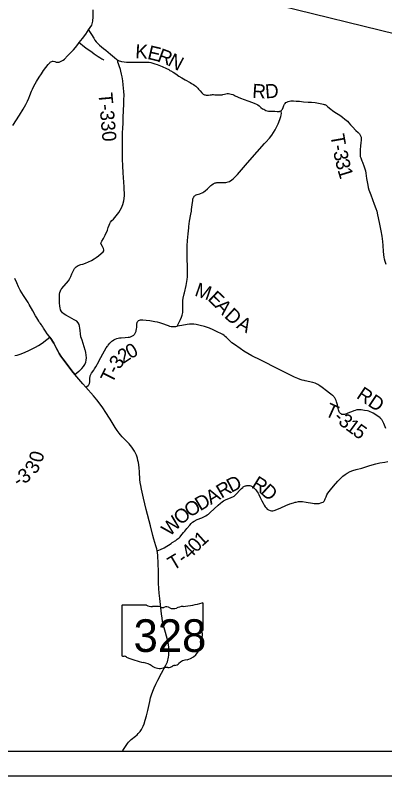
# Model space of a CAD drawing. Extents: x 0 to 34, y 0 to 22.
# Drawn here: x 5.01 to 6.504, y 14.105 to 17.181 of the extents above; entities that cross this region are included whole.
import ezdxf

# ---------------------------------------------------------------- set-up
doc = ezdxf.new("R2010")
doc.units = 0
for name, color, linetype in [('GM_X_State_Location', 7, 'Continuous'), ('GM_X_State_Route', 7, 'Continuous'), ('GM_X_State_Shield', 7, 'Continuous'), ('GM_X_Township_Road', 7, 'Continuous'), ('GM_X_Township_Road_Text', 7, 'Continuous'), ('SH_Data', 7, 'Continuous'), ('SH_Text', 7, 'Continuous')]:
    doc.layers.add(name, color=color, linetype=linetype)

msp = doc.modelspace()

# ---------------------------------------------------------------- linework, layer by layer
at = {"layer": 'GM_X_State_Route'}
for points in [[(5.18, 16.9909), (5.182, 16.9906), (5.1849, 16.9907), (5.1879, 16.9912), (5.1907, 16.992), (5.1935, 16.9932), (5.1988, 16.9961), (5.2038, 16.9997), (5.2085, 17.0037), (5.2216, 17.0168), (5.2451, 17.0414), (5.2534, 17.0505), (5.2631, 17.0625), (5.2689, 17.07), (5.2819, 17.087), (5.2948, 17.1043), (5.3018, 17.1145), (5.306, 17.1215), (5.3192, 17.1407), (5.3242, 17.1566), (5.3254, 17.1744), (5.3247, 17.2033)], [(5.0005, 16.7353), (5.0271, 16.7772), (5.0415, 16.8011), (5.0522, 16.82), (5.0594, 16.8337), (5.0648, 16.8449), (5.0694, 16.8563), (5.0761, 16.8737), (5.0798, 16.8822), (5.0854, 16.8934), (5.096, 16.9124), (5.107, 16.931), (5.1155, 16.944), (5.1245, 16.9567), (5.134, 16.969), (5.1435, 16.9812), (5.1496, 16.9883), (5.1518, 16.9907), (5.1544, 16.9927), (5.1574, 16.994), (5.1607, 16.9947), (5.1639, 16.9945), (5.1701, 16.9932), (5.176, 16.9915), (5.179, 16.991), (5.18, 16.9909)], [(5.1495, 15.8791), (5.1468, 15.8825), (5.1394, 15.8924), (5.1324, 15.9028), (5.1245, 15.916), (5.1211, 15.921), (5.1173, 15.9257), (5.1157, 15.9285), (5.1101, 15.9358), (5.1085, 15.9385), (5.1071, 15.9414), (5.105, 15.9439), (5.0968, 15.9577), (5.0921, 15.9659), (5.0805, 15.9854), (5.0666, 16.0109), (5.0618, 16.0189), (5.0431, 16.0474), (5.0304, 16.069), (5.0232, 16.0827), (5.0158, 16.0988), (5.0089, 16.1158)], [(5.2023, 15.7918), (5.1945, 15.8023), (5.1876, 15.8127), (5.1829, 15.8207), (5.1762, 15.8333), (5.1657, 15.8546), (5.1612, 15.8626), (5.1561, 15.8703), (5.1495, 15.8791)], [(5.2506, 15.7282), (5.2388, 15.7427), (5.2238, 15.7625), (5.2023, 15.7918)], [(5.3937, 15.5479), (5.3916, 15.5514), (5.3765, 15.5749), (5.3643, 15.5929), (5.3534, 15.6079), (5.3401, 15.6251), (5.3261, 15.6417), (5.2954, 15.6767), (5.2831, 15.6907), (5.2506, 15.7282)], [(5.443, 14.2054), (5.4448, 14.208), (5.4638, 14.2364), (5.4677, 14.2414), (5.472, 14.2459), (5.4791, 14.2521), (5.4961, 14.2656), (5.5031, 14.2717), (5.5076, 14.2759), (5.5117, 14.2805), (5.5156, 14.2852), (5.5207, 14.2929), (5.5238, 14.2982), (5.5276, 14.3066), (5.5308, 14.3153), (5.5355, 14.3301), (5.5404, 14.348), (5.5455, 14.3691), (5.5536, 14.4055), (5.5575, 14.4205), (5.5612, 14.4324), (5.5663, 14.4471), (5.572, 14.4616), (5.5783, 14.4758), (5.5864, 14.4927), (5.6009, 14.5201), (5.6188, 14.5528), (5.6229, 14.5611), (5.6253, 14.5668), (5.6272, 14.5726), (5.6288, 14.5785), (5.63, 14.5845), (5.6312, 14.5936), (5.6316, 14.6029), (5.6314, 14.6121), (5.6305, 14.6245), (5.6291, 14.6368), (5.6274, 14.6459), (5.624, 14.661), (5.6152, 14.694), (5.6087, 14.718), (5.6059, 14.7301), (5.6037, 14.7423), (5.6011, 14.7608), (5.594, 14.8225), (5.592, 14.8442), (5.5907, 14.8628), (5.5899, 14.8845), (5.589, 14.9197), (5.5887, 14.9311), (5.586, 14.9962), (5.5851, 15.0085), (5.5842, 15.015), (5.5823, 15.0236), (5.5791, 15.0355), (5.5709, 15.0623), (5.5669, 15.0773), (5.557, 15.1164), (5.5397, 15.1825), (5.5285, 15.2277), (5.5203, 15.2641), (5.5173, 15.2794), (5.5155, 15.2917), (5.5143, 15.3041), (5.5128, 15.3351), (5.5115, 15.3506), (5.5099, 15.3629), (5.5084, 15.372), (5.5063, 15.381), (5.5038, 15.3899), (5.4998, 15.4017), (5.4963, 15.4102), (5.4921, 15.4184), (5.4873, 15.4263), (5.482, 15.4339), (5.4763, 15.4412), (5.4703, 15.4483), (5.4618, 15.4573), (5.4418, 15.4766), (5.4355, 15.4836), (5.4296, 15.4909), (5.4224, 15.5011), (5.414, 15.5142), (5.3937, 15.5479)]]:
    msp.add_lwpolyline(points, dxfattribs=at)
at = {"layer": 'GM_X_State_Shield'}
for p, q in [((5.5406, 14.7959), (5.4441, 14.7959)), ((5.7705, 14.6962), (5.7705, 14.8009)), ((5.4409, 14.7925), (5.4409, 14.5923)), ((5.7704, 14.6962), (5.7705, 14.6962))]:
    msp.add_line(p, q, dxfattribs=at)
for centre, major_axis, start_param, end_param in [((5.4447, 14.7929), (0.00382, 0), 1.712693, 3.28349), ((5.5636, 14.8191), (0.037, 0), 4.042523, 4.731795), ((5.6531, 15.0687), (0.3495, 0), 4.814394, 5.042369), ((5.7668, 14.8013), (0.00367, 0), 6.141152, 7.989035), ((5.5759, 14.6835), (0.133, 0), 1.404758, 1.657858), ((5.6061, 14.7939), (0.0107, 0), 3.836095, 5.185415), ((5.6218, 14.7708), (0.0222, 0), 0.950623, 2.079405), ((5.6504, 14.8025), (0.0267, 0), 4.081561, 5.145723), ((5.6976, 14.7348), (0.0703, 0), 1.699011, 2.107814), ((5.7696, 14.6885), (0.00568, 0), 1.883978, 3.671073), ((5.7335, 14.6753), (0.0341, 0), 5.934695, 6.695948), ((5.7665, 14.6958), (0.00393, 0), 5.05454, 6.418171), ((5.6726, 14.639), (0.0874, 0), 5.101752, 6.440018), ((5.7836, 14.6524), (0.0248, 0), 2.387724, 3.262537), ((5.4447, 14.5919), (0.00385, 0), 3.00124, 4.508301), ((5.4453, 14.6124), (0.0294, 0), 4.665946, 4.897461), ((5.4513, 14.5808), (0.0106, 0), 0.519207, 1.627899), ((5.5851, 14.7606), (0.2524, 0), 4.195997, 4.488961), ((5.5099, 14.5024), (0.079, 0), 0.823519, 1.323587), ((5.5953, 14.5798), (0.0501, 0), 4.026481, 4.996735), ((5.6279, 14.5648), (0.0267, 0), 4.691044, 5.507374), ((5.652, 14.5454), (0.00752, 0), 1.147584, 2.315152), ((5.6488, 14.5729), (0.0282, 0), 4.937069, 5.64225), ((5.7095, 14.5362), (0.0479, 0), 1.647645, 2.488434), ((5.6242, 14.5106), (0.0412, 0), 1.495662, 1.94098)]:
    msp.add_ellipse(centre, major_axis=major_axis, ratio=0.8, start_param=start_param, end_param=end_param, dxfattribs=at)
at = {"layer": 'GM_X_Township_Road'}
for points in [[(5.306, 17.1215), (5.3127, 17.1109), (5.3177, 17.1031), (5.3271, 17.0875), (5.332, 17.0802), (5.3375, 17.0729), (5.3438, 17.0661), (5.3506, 17.0601), (5.367, 17.0469), (5.3762, 17.0396), (5.3947, 17.0239), (5.4111, 17.0098), (5.4209, 17.0018), (5.4254, 16.9986), (5.4298, 16.9968), (5.4354, 16.9952), (5.4399, 16.994), (5.4413, 16.9937), (5.4505, 16.9921), (5.4597, 16.9913), (5.469, 16.9909), (5.495, 16.9911), (5.5217, 16.9917), (5.5403, 16.9917), (5.5446, 16.9913), (5.5509, 16.9905), (5.5581, 16.9894), (5.5664, 16.9874), (5.5747, 16.9848), (5.5835, 16.9818), (5.6043, 16.9737), (5.6215, 16.9654), (5.6308, 16.9608), (5.6357, 16.9579), (5.6394, 16.9554), (5.6484, 16.9503), (5.6592, 16.9433), (5.6718, 16.9349), (5.6837, 16.9275), (5.6964, 16.9202), (5.717, 16.9087), (5.7233, 16.9053), (5.7309, 16.9006), (5.7365, 16.8968), (5.7407, 16.8935), (5.7449, 16.8897), (5.748, 16.8861), (5.7515, 16.8818), (5.7571, 16.8748), (5.7639, 16.8667), (5.7667, 16.8638), (5.7696, 16.8615), (5.7721, 16.8603), (5.7748, 16.8594), (5.7774, 16.8588), (5.7814, 16.8582), (5.7858, 16.8579), (5.7917, 16.8582), (5.7985, 16.859), (5.804, 16.8595), (5.8071, 16.8597), (5.8114, 16.8597), (5.8164, 16.8596), (5.8253, 16.8596), (5.8363, 16.8595), (5.8421, 16.8595), (5.846, 16.8596), (5.85, 16.86), (5.8558, 16.862), (5.8614, 16.8633), (5.8673, 16.8638), (5.8728, 16.8637), (5.8778, 16.8632), (5.8829, 16.8623), (5.8893, 16.8603), (5.8954, 16.8575), (5.8993, 16.8554), (5.9213, 16.8452), (5.9504, 16.8346), (5.9687, 16.8277), (5.9781, 16.8241), (5.9857, 16.8208), (5.9915, 16.8181), (5.9968, 16.8142), (6.0036, 16.808), (6.0104, 16.803), (6.0145, 16.8004), (6.0186, 16.7978), (6.023, 16.7957), (6.0284, 16.794), (6.0334, 16.793), (6.0403, 16.7927), (6.0516, 16.7924), (6.0601, 16.7923), (6.0687, 16.7921), (6.0734, 16.7921), (6.078, 16.7921), (6.0803, 16.7924), (6.0843, 16.7941), (6.0866, 16.796), (6.0884, 16.7982), (6.0904, 16.8012), (6.0931, 16.8079), (6.0955, 16.8157), (6.0969, 16.8184), (6.099, 16.8215), (6.101, 16.8242), (6.1043, 16.8273), (6.1075, 16.8294), (6.1105, 16.831), (6.1138, 16.8322), (6.1185, 16.8336), (6.1242, 16.8343), (6.1293, 16.8345), (6.1357, 16.8344), (6.1459, 16.8339), (6.1539, 16.8332), (6.1592, 16.8328), (6.1761, 16.8312), (6.1946, 16.8298), (6.2084, 16.8289), (6.2224, 16.8277), (6.2366, 16.8257), (6.2497, 16.8232), (6.2557, 16.8216), (6.2597, 16.8202), (6.2615, 16.8195), (6.2643, 16.8182), (6.2669, 16.8166), (6.2695, 16.8149), (6.2742, 16.811), (6.286, 16.8007), (6.2922, 16.7954), (6.2981, 16.7912), (6.3094, 16.7845), (6.3221, 16.7771), (6.3339, 16.7685), (6.3425, 16.761), (6.3529, 16.7522), (6.3591, 16.7454), (6.3653, 16.7379), (6.3708, 16.7321), (6.374, 16.729), (6.3872, 16.7154), (6.396, 16.7072), (6.3995, 16.7041), (6.4017, 16.7016), (6.4036, 16.6992), (6.4052, 16.6965), (6.4066, 16.6938), (6.4076, 16.6909), (6.4083, 16.688), (6.4088, 16.685), (6.4089, 16.682), (6.4087, 16.6758), (6.4077, 16.6646), (6.4064, 16.6523), (6.405, 16.6368), (6.4046, 16.6275), (6.4045, 16.6217), (6.4046, 16.6153), (6.4053, 16.61), (6.4068, 16.6047), (6.4086, 16.5998), (6.4117, 16.5915), (6.4137, 16.5868), (6.4211, 16.5677), (6.4236, 16.5599), (6.4259, 16.5512), (6.4277, 16.5422), (6.4291, 16.5313), (6.4304, 16.5206), (6.4326, 16.5073), (6.4355, 16.4931), (6.4375, 16.484), (6.4402, 16.4751), (6.4477, 16.4548), (6.4615, 16.4173), (6.4678, 16.3998), (6.4714, 16.3879), (6.4752, 16.3731), (6.4819, 16.3432), (6.4886, 16.3095), (6.4927, 16.288), (6.494, 16.277), (6.4952, 16.2661), (6.4965, 16.2491), (6.4982, 16.2256), (6.4988, 16.2139), (6.5005, 16.2017), (6.5018, 16.1956), (6.5042, 16.1867), (6.5083, 16.1749)], [(5.2689, 17.07), (5.2735, 17.0663), (5.2833, 17.0585), (5.2959, 17.0493), (5.3216, 17.0315), (5.3295, 17.0252), (5.3456, 17.0137), (5.352, 17.0097), (5.3601, 17.0049), (5.3652, 17.0015), (5.3676, 16.9995)], [(5.4433, 16.6481), (5.4436, 16.6658), (5.444, 16.6872), (5.4443, 16.705), (5.445, 16.7245), (5.4457, 16.7443), (5.4467, 16.7691), (5.4473, 16.794), (5.4489, 16.8225), (5.4494, 16.839), (5.4499, 16.8571), (5.4495, 16.8724), (5.4479, 16.886), (5.4464, 16.8995), (5.4444, 16.9157), (5.4422, 16.9319), (5.4401, 16.9431), (5.4375, 16.9553), (5.4358, 16.9613), (5.4302, 16.9765), (5.4272, 16.9847), (5.4254, 16.9907), (5.4251, 16.9949), (5.4254, 16.9986)], [(6.5088, 15.5102), (6.4999, 15.5298), (6.4961, 15.538), (6.4933, 15.5435), (6.4916, 15.546), (6.4896, 15.5484), (6.4874, 15.5506), (6.4851, 15.5526), (6.4801, 15.5563), (6.4568, 15.5717), (6.4513, 15.5747), (6.4457, 15.5772), (6.4398, 15.5792), (6.4338, 15.5807), (6.4216, 15.5831), (6.4093, 15.585), (6.4031, 15.5855), (6.3969, 15.5854), (6.3908, 15.5846), (6.3847, 15.5831), (6.3788, 15.5812), (6.3701, 15.5778), (6.3617, 15.574), (6.3517, 15.5702), (6.3456, 15.568), (6.3416, 15.5669), (6.3381, 15.5664), (6.3361, 15.5662), (6.3344, 15.5664), (6.3312, 15.567), (6.3278, 15.5684), (6.3249, 15.5704), (6.3227, 15.5726), (6.321, 15.5751), (6.3197, 15.5776), (6.3185, 15.5809), (6.3174, 15.585), (6.3162, 15.5903), (6.3127, 15.6054), (6.3095, 15.6174), (6.3074, 15.6233), (6.3048, 15.6289), (6.3016, 15.6342), (6.2998, 15.6367), (6.2978, 15.639), (6.2956, 15.6412), (6.2933, 15.6433), (6.2909, 15.6452), (6.2807, 15.6523), (6.2682, 15.6615), (6.2511, 15.675), (6.2412, 15.6825), (6.2334, 15.6876), (6.2279, 15.6904), (6.2221, 15.6927), (6.2131, 15.6953), (6.1828, 15.7021), (6.1783, 15.7032), (6.1708, 15.7052), (6.1619, 15.708), (6.1532, 15.7115), (6.1391, 15.7179), (6.075, 15.7496), (6.0028, 15.7858), (5.9668, 15.8042), (5.9505, 15.8132), (5.9345, 15.8228), (5.9189, 15.8331), (5.896, 15.8491), (5.886, 15.8565), (5.8789, 15.8625), (5.8744, 15.8668), (5.8636, 15.878), (5.859, 15.8822), (5.8542, 15.8861), (5.8491, 15.8896), (5.841, 15.8941), (5.8298, 15.8997), (5.8101, 15.9088), (5.7958, 15.9149), (5.787, 15.9181), (5.7751, 15.9218), (5.7571, 15.9265), (5.7419, 15.9298), (5.7327, 15.9314), (5.7265, 15.9321), (5.7203, 15.9322), (5.7141, 15.9318), (5.7049, 15.9306), (5.6835, 15.9267), (5.6641, 15.9236), (5.6696, 15.9338), (5.6759, 15.9448), (5.6786, 15.9509), (5.6819, 15.9599), (5.6845, 15.9675), (5.6862, 15.9739), (5.6873, 15.9792), (5.6879, 15.9832), (5.6881, 15.992), (5.6876, 16.0083), (5.6878, 16.0218), (5.6881, 16.0271), (5.6894, 16.0364), (5.6928, 16.0537), (5.6939, 16.0586), (5.7007, 16.0879), (5.7038, 16.1041), (5.7053, 16.1118), (5.7065, 16.1233), (5.707, 16.1335), (5.7071, 16.1408), (5.7067, 16.1525), (5.7064, 16.1668), (5.7055, 16.1945), (5.705, 16.2273), (5.7054, 16.248), (5.7063, 16.2697), (5.709, 16.2972), (5.7114, 16.3205), (5.7124, 16.3271), (5.7148, 16.3477), (5.7199, 16.376), (5.722, 16.3881), (5.7233, 16.3947), (5.7259, 16.4145), (5.7276, 16.4311), (5.7287, 16.437), (5.7295, 16.4405), (5.7305, 16.4434), (5.7316, 16.4454), (5.7323, 16.4468), (5.7339, 16.4489), (5.7362, 16.4511), (5.7391, 16.4534), (5.7416, 16.4547), (5.7451, 16.4557), (5.757, 16.4588), (5.7681, 16.4635), (5.7732, 16.4669), (5.778, 16.4708), (5.7871, 16.4791), (5.8006, 16.4917), (5.8054, 16.4955), (5.8106, 16.4989), (5.8133, 16.5003), (5.8161, 16.5015), (5.819, 16.5026), (5.822, 16.5035), (5.825, 16.5041), (5.828, 16.5046), (5.8342, 16.5048), (5.8496, 16.5042), (5.8557, 16.5043), (5.8618, 16.5049), (5.8707, 16.5069), (5.8764, 16.5091), (5.8862, 16.5154), (5.8914, 16.5197), (5.898, 16.5262), (5.9086, 16.5375), (5.9249, 16.5562), (5.9494, 16.5843), (5.9884, 16.6285), (6.0179, 16.6616), (6.0235, 16.6679), (6.0374, 16.6844), (6.0469, 16.6964), (6.0539, 16.7066), (6.0604, 16.7172), (6.0662, 16.7282), (6.0726, 16.7423), (6.0796, 16.7596), (6.0837, 16.7713), (6.0852, 16.7773), (6.086, 16.7847), (6.0855, 16.7899), (6.0843, 16.7941)], [(5.2506, 15.7282), (5.267, 15.7417), (5.2692, 15.7434), (5.2795, 15.7527), (5.2864, 15.7606), (5.2912, 15.769), (5.2948, 15.7775), (5.2972, 15.7867), (5.2976, 15.796), (5.2969, 15.8065), (5.2953, 15.8166), (5.2936, 15.8243), (5.2933, 15.826), (5.2802, 15.8668), (5.2757, 15.8809), (5.2733, 15.8928), (5.272, 15.9062), (5.2711, 15.9153), (5.2703, 15.9239), (5.2687, 15.93), (5.2645, 15.9375), (5.2584, 15.9433), (5.2486, 15.9494), (5.2296, 15.9602), (5.2147, 15.9679), (5.2074, 15.9721), (5.201, 15.9768), (5.1965, 15.9834), (5.1933, 15.9902), (5.1913, 15.9973), (5.1898, 16.0047), (5.1884, 16.0175), (5.1884, 16.0338), (5.1884, 16.0423), (5.1888, 16.0528), (5.19, 16.0597), (5.1927, 16.067), (5.1963, 16.0728), (5.1988, 16.0758), (5.2253, 16.1071), (5.2306, 16.1161), (5.2341, 16.1238), (5.2383, 16.1347), (5.2446, 16.1465), (5.2497, 16.1561), (5.2564, 16.1633), (5.2641, 16.1682), (5.2754, 16.1724), (5.2838, 16.1748), (5.2947, 16.1787), (5.3056, 16.1834), (5.318, 16.1896), (5.3288, 16.1956), (5.3374, 16.201), (5.3466, 16.2077), (5.3577, 16.2168), (5.3656, 16.2239), (5.368, 16.2281), (5.3677, 16.2324), (5.3662, 16.2371), (5.3623, 16.2454), (5.3573, 16.2547), (5.3565, 16.258), (5.3572, 16.2621), (5.3606, 16.2677), (5.3663, 16.2774), (5.3733, 16.2912), (5.3825, 16.3116), (5.3863, 16.3224), (5.3895, 16.3326), (5.3919, 16.3383), (5.3949, 16.3437), (5.4004, 16.3502), (5.4069, 16.3567), (5.4186, 16.3693), (5.4292, 16.3837), (5.4349, 16.393), (5.4392, 16.4019), (5.4451, 16.4152), (5.4495, 16.4302), (5.4507, 16.4398), (5.4517, 16.4518), (5.4516, 16.464), (5.451, 16.4738), (5.4501, 16.4873), (5.4463, 16.544), (5.4444, 16.5721), (5.4434, 16.5992), (5.4433, 16.616), (5.4433, 16.6461), (5.4433, 16.6481)], [(5.3124, 15.7193), (5.3132, 15.7223), (5.3143, 15.7252), (5.3156, 15.728), (5.3187, 15.7333), (5.3278, 15.746), (5.3309, 15.7513), (5.3357, 15.7592), (5.3476, 15.781), (5.3498, 15.7849), (5.3715, 15.8243), (5.378, 15.8354), (5.3826, 15.8423), (5.3838, 15.8436), (5.3858, 15.8465), (5.3921, 15.8544), (5.3964, 15.859), (5.4011, 15.8631), (5.4036, 15.8649), (5.4089, 15.8681), (5.4145, 15.8708), (5.4202, 15.8731), (5.4261, 15.8749), (5.4322, 15.8761), (5.4383, 15.8768), (5.4538, 15.8778), (5.4663, 15.8787), (5.4724, 15.8796), (5.4755, 15.8803), (5.4784, 15.8813), (5.4813, 15.8825), (5.484, 15.884), (5.4866, 15.8857), (5.489, 15.8876), (5.4912, 15.8898), (5.4932, 15.8922), (5.4949, 15.8948), (5.4964, 15.8976), (5.4977, 15.9004), (5.4987, 15.9034), (5.4995, 15.9064), (5.5007, 15.9125), (5.5014, 15.9187), (5.5017, 15.928), (5.5021, 15.9343), (5.5026, 15.9374), (5.5036, 15.9403), (5.5051, 15.943), (5.5072, 15.9452), (5.5089, 15.9463), (5.5126, 15.9481), (5.5158, 15.949), (5.5199, 15.9494), (5.5255, 15.9493), (5.5391, 15.948), (5.5548, 15.9462), (5.5744, 15.9429), (5.5838, 15.9411), (5.5928, 15.9387), (5.6015, 15.9356), (5.6278, 15.9257), (5.6337, 15.9238), (5.6398, 15.9225), (5.646, 15.9219), (5.6522, 15.922), (5.6589, 15.9227), (5.6641, 15.9236)], [(5.0079, 15.8045), (5.0177, 15.8064), (5.034, 15.8118), (5.0502, 15.8181), (5.0652, 15.8252), (5.0787, 15.8322), (5.0914, 15.8387), (5.1039, 15.8457), (5.1186, 15.8549), (5.1375, 15.8696), (5.1495, 15.8791)], [(5.1495, 15.8791), (5.1561, 15.8703), (5.1612, 15.8626), (5.1657, 15.8546), (5.1762, 15.8333), (5.1829, 15.8207), (5.1876, 15.8127), (5.1945, 15.8023), (5.2023, 15.7918)], [(5.2023, 15.7918), (5.2238, 15.7625), (5.2388, 15.7427), (5.2506, 15.7282)], [(5.2954, 15.6767), (5.3001, 15.68), (5.3049, 15.684), (5.307, 15.6862), (5.3087, 15.6888), (5.3099, 15.6916), (5.3108, 15.6946), (5.3113, 15.6977), (5.3115, 15.7008), (5.3115, 15.7101), (5.3119, 15.7163), (5.3124, 15.7193)], [(5.9948, 15.2428), (6.0006, 15.2312), (6.0076, 15.217), (6.0124, 15.208), (6.0167, 15.2001), (6.0208, 15.1934), (6.0244, 15.1883), (6.0288, 15.1842), (6.034, 15.1807), (6.0404, 15.1781), (6.0461, 15.1773), (6.0514, 15.1773), (6.0569, 15.1784), (6.0609, 15.1796), (6.0834, 15.1896), (6.1035, 15.1984), (6.1198, 15.2048), (6.1349, 15.2094), (6.1417, 15.2112), (6.146, 15.2123), (6.1554, 15.2141), (6.1613, 15.2149), (6.1667, 15.2151), (6.1721, 15.2149), (6.1863, 15.2121), (6.2115, 15.2072), (6.2182, 15.2064), (6.2248, 15.2061), (6.2314, 15.2062), (6.2386, 15.207), (6.245, 15.2085), (6.2498, 15.2099), (6.2551, 15.2125), (6.259, 15.2162), (6.2618, 15.2209), (6.2638, 15.2259), (6.2668, 15.2339), (6.2704, 15.2416), (6.2742, 15.2487), (6.2788, 15.2553), (6.2843, 15.2617), (6.2967, 15.2771), (6.3144, 15.2969), (6.3245, 15.3075), (6.3343, 15.3167), (6.3438, 15.3242), (6.3525, 15.3297), (6.3642, 15.3355), (6.375, 15.3393), (6.3887, 15.3435), (6.4116, 15.3498), (6.4431, 15.3595), (6.4677, 15.3664), (6.4836, 15.3704), (6.5039, 15.374), (6.5164, 15.3758)], [(5.5842, 15.015), (5.5972, 15.0202), (5.6124, 15.0278), (5.6401, 15.0449), (5.6451, 15.0485), (5.6594, 15.0573), (5.6653, 15.0619), (5.6726, 15.0676), (5.677, 15.0721), (5.6799, 15.0752), (5.6907, 15.0894), (5.6958, 15.0949), (5.7041, 15.1049), (5.7153, 15.1186), (5.7216, 15.1253), (5.7268, 15.1304), (5.7341, 15.1354), (5.7453, 15.1414), (5.7644, 15.1488), (5.7729, 15.1526), (5.7812, 15.157), (5.7865, 15.1603), (5.7915, 15.1639), (5.7986, 15.1699), (5.8145, 15.1848), (5.8304, 15.1997), (5.8397, 15.2079), (5.8472, 15.2136), (5.8524, 15.217), (5.8605, 15.2215), (5.869, 15.2255), (5.8806, 15.23), (5.8864, 15.2322), (5.8892, 15.2335), (5.892, 15.235), (5.8946, 15.2367), (5.8995, 15.2405), (5.9062, 15.2469), (5.9167, 15.2585), (5.9251, 15.2676), (5.9297, 15.2717), (5.9322, 15.2736), (5.9349, 15.2752), (5.9376, 15.2766), (5.9406, 15.2777), (5.9436, 15.2785), (5.9466, 15.279), (5.9497, 15.2793), (5.9528, 15.2793), (5.9559, 15.2792), (5.959, 15.2788), (5.962, 15.2781), (5.9649, 15.277), (5.9703, 15.2736), (5.9759, 15.2688), (5.9824, 15.2612), (5.9878, 15.2543), (5.9919, 15.2476), (5.9948, 15.2428)]]:
    msp.add_lwpolyline(points, dxfattribs=at)
at = {"layer": 'SH_Data'}
for p, q in [((1.9763, 14.2054), (8.7763, 14.2054)), ((1.8763, 14.1054), (8.8763, 14.1054))]:
    msp.add_line(p, q, dxfattribs=at)
at = {"layer": 'SH_Text'}
msp.add_lwpolyline([(5.3474, 17.401), (9.2222, 16.4501), (9.2222, 16.8603)], close=True, dxfattribs=at)

# ---------------------------------------------------------------- texts
at = {"layer": 'GM_X_State_Location'}
for s in ['s', 'r']:
    msp.add_text(s, height=0.000189, dxfattribs=at).set_placement((5.602, 14.6791))
msp.add_text('328', height=0.000189, rotation=0, dxfattribs=at).set_placement((5.5351, 14.6653))
at = {"layer": 'GM_X_State_Shield'}
msp.add_text('328', height=0.13184, dxfattribs=at).set_placement((5.4885, 14.6064))
at = {"layer": 'GM_X_Township_Road_Text'}
for s, height, rotation, p in [('K', 0.0568, 356.8913, (5.4942, 17.0072)), ('E', 0.0568, 346.4481, (5.5414, 17.0049)), ('R', 0.0568, 339.5874, (5.581, 16.9954)), ('N', 0.0568, 332.0696, (5.623, 16.98)), ('R', 0.0568, 356.1646, (5.967, 16.8474)), ('D', 0.0568, 4.3993, (6.0223, 16.8443)), ('T-330', 0.05682, 275.0665, (5.346, 16.8655)), ('T', 0.0568, 280.0281, (6.2838, 16.6954)), ('-', 0.0568, 280.3623, (6.2913, 16.6532)), ('3', 0.0568, 281.5638, (6.2957, 16.629)), ('3', 0.0568, 283.9053, (6.3033, 16.5922)), ('1', 0.0568, 287.0564, (6.3126, 16.555)), ('M', 0.0568, 341.0074, (5.7321, 16.0477)), ('E', 0.0568, 316.5365, (5.785, 16.0309)), ('A', 0.0568, 311.8096, (5.815, 16.0026)), ('D', 0.0568, 317.3104, (5.8525, 15.9611)), ('A', 0.0568, 331.3239, (5.9015, 15.9183)), ('0', 0.0568, 28.9677, (5.4753, 15.7893)), ('2', 0.0568, 33.5501, (5.4471, 15.7705)), ('3', 0.0568, 54.7019, (5.4308, 15.7458)), ('T', 0.0568, 63.1609, (5.4023, 15.6888)), ('-', 0.0568, 63.3234, (5.4215, 15.7269)), ('RD', 0.05682, 326.5838, (6.3862, 15.6348)), ('T', 0.0568, 335.6511, (6.2583, 15.5635)), ('-', 0.0568, 319.077, (6.2934, 15.5484)), ('3', 0.0568, 320.9813, (6.3126, 15.5317)), ('1', 0.0568, 323.782, (6.3422, 15.5079)), ('5', 0.0568, 324.1616, (6.3708, 15.4869)), ('0', 0.0568, 75.5096, (5.1184, 15.3688)), ('3', 0.0568, 57.56, (5.092, 15.3215)), ('3', 0.0568, 32.8614, (5.0439, 15.2838)), ('D', 0.0568, 27.624, (5.8834, 15.2489)), ('R', 0.0568, 328.0319, (5.9611, 15.2727)), ('-', 0.0568, 30.6944, (5.0218, 15.2706)), ('R', 0.0568, 30.4711, (5.8438, 15.2256)), ('D', 0.0568, 317.5677, (5.9982, 15.2498)), ('A', 0.0568, 30.6414, (5.8008, 15.2001)), ('D', 0.0568, 30.6639, (5.7578, 15.1746)), ('O', 0.0568, 32.2077, (5.7159, 15.1482)), ('O', 0.0568, 41.0454, (5.68, 15.1167)), ('W', 0.0568, 45.6065, (5.6348, 15.0705)), ('1', 0.0568, 41.9369, (5.7649, 15.0302)), ('4', 0.0568, 44.0571, (5.7146, 14.9787)), ('0', 0.0568, 47.2529, (5.7421, 15.0055)), ('T', 0.0568, 30.9197, (5.6483, 14.9341)), ('-', 0.0568, 37.2313, (5.6904, 14.9598))]:
    msp.add_text(s, height=height, rotation=rotation, dxfattribs=at).set_placement(p)

doc.saveas('drawing.dxf')
